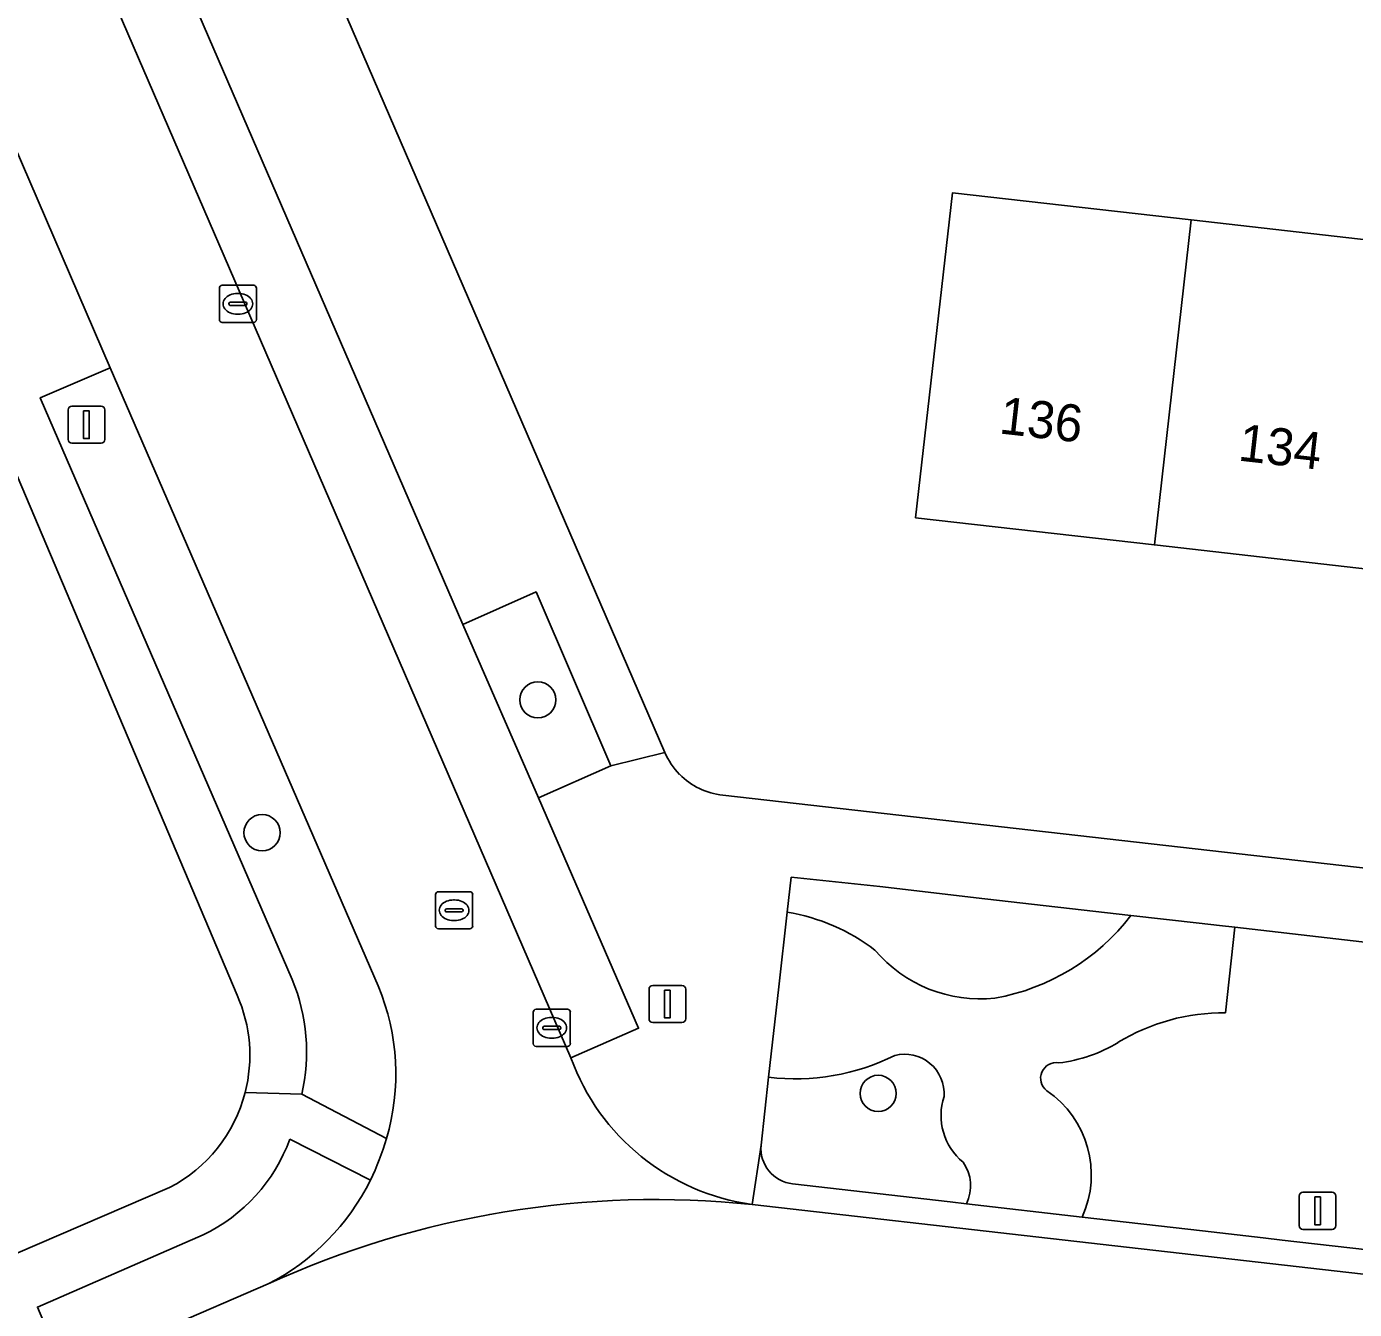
# Model space of a CAD drawing. Extents: x 162026 to 163502, y 387295 to 388169.
# Drawn here: x 162241.43 to 162277.28, y 387988.1 to 388022.74 of the extents above; entities that cross this region are included whole.
import ezdxf

# ---------------------------------------------------------------- set-up
doc = ezdxf.new("R2010")
doc.units = 0
for name, color, linetype in [('IMGEO_Boom', 7, 'Continuous'), ('IMGEO_Erf', 7, 'Continuous'), ('IMGEO_Groenvoorziening', 7, 'Continuous'), ('IMGEO_Kolk', 7, 'Continuous'), ('IMGEO_Lichtmast', 7, 'Continuous'), ('IMGEO_Pand', 7, 'Continuous'), ('IMGEO_Pand_nummerreeks', 7, 'Continuous'), ('IMGEO_Parkeervlak_open', 7, 'Continuous'), ('IMGEO_Rijbaan_lokaal_open', 7, 'Continuous'), ('IMGEO_Rioolput', 7, 'Continuous'), ('IMGEO_Voetpad_open', 7, 'Continuous')]:
    doc.layers.add(name, color=color, linetype=linetype)

msp = doc.modelspace()

# ---------------------------------------------------------------- linework, layer by layer
at = {"layer": 'IMGEO_Boom'}
for centre in [(162255.234, 388004.559), (162247.788, 388000.972), (162264.422, 387993.931)]:
    msp.add_circle(centre, 0.489, dxfattribs=at)
at = {"layer": 'IMGEO_Erf'}
for points in [[(162299.337, 388025.532), (162289.611, 388026.623), (162289.188, 388022.806), (162286.544, 388023.099), (162283.9, 388023.392), (162284.323, 388027.209), (162276.998, 388028.02), (162276.575, 388024.203), (162273.921, 388024.497), (162271.278, 388024.79), (162271.7, 388028.607), (162270.784, 388028.723), (162270.329, 388028.733), (162270.019, 388028.709), (162269.435, 388028.585), (162250.08, 388022.997), (162258.662, 388003.139)], [(162247.117, 387996.582), (162240.422, 388012.373)], [(162260.226, 388001.984), (162277.731, 388000), (162292.907, 387998.354), (162293.134, 387998.329)], [(162231.639, 387985.507), (162245.293, 387991.388)]]:
    msp.add_lwpolyline(points, dxfattribs=at)
msp.add_lwpolyline([(162279.335, 388016.79), (162279.673, 388019.771), (162286.03, 388019.05), (162292.043, 388018.368), (162291.704, 388015.385), (162292.241, 388015.324), (162291.244, 388006.545), (162284.696, 388007.289), (162278.339, 388008.01), (162271.878, 388008.744), (162265.433, 388009.476), (162266.429, 388018.255), (162272.875, 388017.523)], close=True, dxfattribs=at)
for centre, radius, start, end in [((162260.416, 388003.89), 1.908, 203.1954, 224.72), ((162260.432, 388003.898), 1.925, 224.5303, 263.8431), ((162243.429, 387994.956), 4.03, 345.5537, 23.7898), ((162243.434, 387994.96), 4.027, 297.4986, 345.4932)]:
    msp.add_arc(centre, radius, start, end, dxfattribs=at)
at = {"layer": 'IMGEO_Groenvoorziening'}
for points in [[(162243.691, 388013.525), (162241.8, 388012.719), (162248.605, 387997.004)], [(162250.922, 387996.833), (162243.691, 388013.525)], [(162271.244, 387998.739), (162267.305, 387999.189), (162264.468, 387999.514), (162262.073, 387999.77), (162261.967, 387998.826)], [(162261.967, 387998.826), (162261.74, 387996.813), (162261.465, 387994.365)], [(162274.047, 387998.418), (162273.64, 387998.465), (162273.085, 387998.528), (162271.244, 387998.739)], [(162273.802, 387996.107), (162274.047, 387998.418)], [(162284.991, 387997.166), (162282.29, 387997.475), (162281.785, 387997.533), (162279.507, 387997.794), (162274.047, 387998.418), (162273.802, 387996.107)], [(162269.927, 387990.591), (162273.177, 387990.217), (162274.818, 387990.029), (162275.326, 387989.971), (162280.015, 387989.433), (162283.986, 387988.977), (162284.111, 387988.963), (162284.576, 387993.299), (162284.991, 387997.166)], [(162261.465, 387994.365), (162261.259, 387992.534)], [(162248.859, 387993.907), (162251.148, 387992.708)], [(162250.717, 387991.588), (162248.537, 387992.693)], [(162262.113, 387991.488), (162266.366, 387991), (162266.807, 387990.949)], [(162266.807, 387990.949), (162269.927, 387990.591)], [(162246.195, 387990.109), (162241.722, 387988.158), (162242.466, 387986.409), (162247.956, 387988.784)]]:
    msp.add_lwpolyline(points, dxfattribs=at)
msp.add_lwpolyline([(162255.188, 388007.476), (162253.211, 388006.595), (162255.25, 388001.914), (162257.203, 388002.781)], close=True, dxfattribs=at)
for centre, radius, start, end in [((162261.086, 387993.546), 5.353, 52.6247, 80.5234), ((162261.086, 387993.546), 5.353, 52.6247, 80.5234), ((162266.56, 388002.302), 5.885, 279.9183, 322.7411), ((162266.56, 388002.302), 5.885, 279.9183, 322.7411), ((162267.173, 388000.201), 3.717, 220.2268, 276.1887), ((162267.173, 388000.201), 3.717, 220.2268, 276.1887), ((162243.849, 387995.055), 5.14, 347.0935, 22.2838), ((162245.219, 387994.452), 6.18, 343.6106, 22.6614), ((162273.756, 387990.603), 5.505, 89.5202, 121.2405), ((162273.756, 387990.603), 5.505, 89.5202, 121.2405), ((162268.883, 387998.552), 3.819, 276.236, 301.8945), ((162268.883, 387998.552), 3.819, 276.236, 301.8945), ((162262.177, 388000.359), 6.036, 263.228, 296.4979), ((162262.177, 388000.359), 6.036, 263.228, 296.4979), ((162265.133, 387993.92), 1.07, 356.1314, 104.2236), ((162265.133, 387993.92), 1.07, 356.1314, 104.2236), ((162269.229, 387994.339), 0.422, 80.6533, 232.729), ((162269.229, 387994.339), 0.422, 80.6533, 232.729), ((162267.759, 387993.335), 1.641, 161.7948, 230.4109), ((162267.759, 387993.335), 1.641, 161.7948, 230.4109), ((162267.428, 387991.732), 2.748, 335.464, 55.747), ((162267.428, 387991.732), 2.748, 335.464, 55.747), ((162244.203, 387994.267), 4.611, 295.5909, 340.0341), ((162262.224, 387992.45), 0.969, 175.0512, 263.4082), ((162265.824, 387991.432), 1.095, 333.8593, 35.7187), ((162265.824, 387991.432), 1.095, 333.8593, 35.7187), ((162245.037, 387994.419), 6.346, 297.3808, 333.5046)]:
    msp.add_arc(centre, radius, start, end, dxfattribs=at)
at = {"layer": 'IMGEO_Kolk'}
for p, q in [((162246.636, 388014.829), (162246.636, 388015.681)), ((162246.711, 388015.755), (162247.563, 388015.755)), ((162247.637, 388015.681), (162247.637, 388014.829)), ((162246.938, 388015.298), (162247.336, 388015.298)), ((162247.124, 388015.535), (162247.149, 388015.535)), ((162246.895, 388015.249), (162246.895, 388015.261)), ((162247.333, 388015.212), (162246.935, 388015.212)), ((162247.147, 388014.975), (162247.122, 388014.975)), ((162247.379, 388015.261), (162247.379, 388015.249)), ((162247.563, 388014.755), (162246.711, 388014.755)), ((162255.11, 387995.275), (162255.11, 387996.127)), ((162255.185, 387996.201), (162256.037, 387996.201)), ((162255.598, 387995.981), (162255.623, 387995.981)), ((162256.111, 387996.127), (162256.111, 387995.275)), ((162255.369, 387995.695), (162255.369, 387995.707)), ((162255.807, 387995.658), (162255.409, 387995.658)), ((162255.412, 387995.744), (162255.81, 387995.744)), ((162255.853, 387995.707), (162255.853, 387995.695)), ((162256.037, 387995.201), (162255.185, 387995.201)), ((162255.621, 387995.421), (162255.596, 387995.421))]:
    msp.add_line(p, q, dxfattribs=at)
for points in [[(162246.636, 388014.829), (162246.636, 388015.681)], [(162246.711, 388015.755), (162247.563, 388015.755)], [(162247.637, 388015.681), (162247.637, 388014.829)], [(162247.563, 388014.755), (162246.711, 388014.755)], [(162255.11, 387995.275), (162255.11, 387996.127)], [(162255.185, 387996.201), (162256.037, 387996.201)], [(162256.111, 387996.127), (162256.111, 387995.275)], [(162256.037, 387995.201), (162255.185, 387995.201)]]:
    msp.add_lwpolyline(points, dxfattribs=at)
for centre, radius, start, end in [((162246.713, 388015.679), 0.0765, 91.552, 178.448), ((162246.713, 388015.679), 0.0765, 91.552, 178.448), ((162247.561, 388015.679), 0.0765, 1.552, 88.448), ((162247.561, 388015.679), 0.0765, 1.552, 88.448), ((162246.935, 388015.258), 0.0403, 85.8775, 175.7526), ((162247.34, 388015.26), 0.0386, 1.7309, 96.639), ((162246.932, 388015.248), 0.0366, 178.938, 274.7102), ((162247.336, 388015.255), 0.043, 264.8664, 352.4533), ((162246.713, 388014.831), 0.0765, 181.552, 268.448), ((162246.713, 388014.831), 0.0765, 181.552, 268.448), ((162247.561, 388014.831), 0.0765, 271.552, 358.448), ((162247.561, 388014.831), 0.0765, 271.552, 358.448), ((162255.187, 387996.125), 0.0765, 91.552, 178.448), ((162255.187, 387996.125), 0.0765, 91.552, 178.448), ((162256.035, 387996.125), 0.0765, 1.552, 88.448), ((162256.035, 387996.125), 0.0765, 1.552, 88.448), ((162255.409, 387995.704), 0.0403, 85.8775, 175.7526), ((162255.406, 387995.694), 0.0366, 178.938, 274.7102), ((162255.81, 387995.701), 0.043, 264.8664, 352.4533), ((162255.814, 387995.706), 0.0386, 1.7309, 96.639), ((162255.187, 387995.277), 0.0765, 181.552, 268.448), ((162255.187, 387995.277), 0.0765, 181.552, 268.448), ((162256.035, 387995.277), 0.0765, 271.552, 358.448), ((162256.035, 387995.277), 0.0765, 271.552, 358.448)]:
    msp.add_arc(centre, radius, start, end, dxfattribs=at)
for centre, major_axis, ratio, start_param, end_param in [((162247.123, 388015.255), (-0.387, 0.002), 0.722429, 4.712389, 7.853982), ((162247.148, 388015.255), (-0.39, 0.002), 0.717154, 1.570796, 4.712389), ((162255.597, 387995.701), (-0.387, 0.002), 0.722429, 4.712389, 7.853982), ((162255.622, 387995.701), (-0.39, 0.002), 0.717154, 1.570796, 4.712389)]:
    msp.add_ellipse(centre, major_axis=major_axis, ratio=ratio, start_param=start_param, end_param=end_param, dxfattribs=at)
at = {"layer": 'IMGEO_Lichtmast'}
for p, q in [((162242.652, 388012.49), (162243.442, 388012.49)), ((162243.442, 388012.49), (162242.652, 388012.49)), ((162242.552, 388011.59), (162242.552, 388012.39)), ((162242.552, 388012.39), (162242.552, 388011.59)), ((162243.542, 388012.39), (162243.542, 388011.59)), ((162243.542, 388011.59), (162243.542, 388012.39)), ((162243.442, 388011.49), (162242.652, 388011.49)), ((162242.652, 388011.49), (162243.442, 388011.49)), ((162258.235, 387995.943), (162258.235, 387996.743)), ((162258.235, 387996.743), (162258.235, 387995.943)), ((162258.335, 387996.843), (162259.125, 387996.843)), ((162259.125, 387996.843), (162258.335, 387996.843)), ((162259.225, 387996.743), (162259.225, 387995.943)), ((162259.225, 387995.943), (162259.225, 387996.743)), ((162259.125, 387995.843), (162258.335, 387995.843)), ((162258.335, 387995.843), (162259.125, 387995.843)), ((162275.889, 387991.259), (162276.679, 387991.259)), ((162276.679, 387991.259), (162275.889, 387991.259)), ((162275.789, 387990.359), (162275.789, 387991.159)), ((162275.789, 387991.159), (162275.789, 387990.359)), ((162276.779, 387991.159), (162276.779, 387990.359)), ((162276.779, 387990.359), (162276.779, 387991.159)), ((162276.679, 387990.259), (162275.889, 387990.259)), ((162275.889, 387990.259), (162276.679, 387990.259))]:
    msp.add_line(p, q, dxfattribs=at)
for points in [[(162242.972, 388012.365), (162243.122, 388012.365), (162243.122, 388011.615), (162242.972, 388011.615), (162242.972, 388012.365)], [(162258.655, 387996.718), (162258.805, 387996.718), (162258.805, 387995.968), (162258.655, 387995.968), (162258.655, 387996.718)], [(162276.209, 387991.134), (162276.359, 387991.134), (162276.359, 387990.384), (162276.209, 387990.384), (162276.209, 387991.134)]]:
    msp.add_lwpolyline(points, dxfattribs=at)
for centre, start, end in [((162242.652, 388012.39), 90, 180), ((162242.652, 388012.39), 90, 180), ((162243.442, 388012.39), 0, 90), ((162243.442, 388012.39), 360, 90), ((162242.652, 388011.59), 180, 270), ((162242.652, 388011.59), 180, 270), ((162243.442, 388011.59), 270, 0), ((162243.442, 388011.59), 270, 0), ((162258.335, 387996.743), 90, 180), ((162258.335, 387996.743), 90, 180), ((162259.125, 387996.743), 0, 90), ((162259.125, 387996.743), 360, 90), ((162258.335, 387995.943), 180, 270), ((162258.335, 387995.943), 180, 270), ((162259.125, 387995.943), 270, 0), ((162259.125, 387995.943), 270, 0), ((162275.889, 387991.159), 90, 180), ((162275.889, 387991.159), 90, 180), ((162276.679, 387991.159), 0, 90), ((162276.679, 387991.159), 360, 90), ((162275.889, 387990.359), 180, 270), ((162275.889, 387990.359), 180, 270), ((162276.679, 387990.359), 270, 0), ((162276.679, 387990.359), 270, 0)]:
    msp.add_arc(centre, 0.1, start, end, dxfattribs=at)
at = {"layer": 'IMGEO_Pand'}
for points in [[(162272.875, 388017.523), (162266.429, 388018.255), (162265.433, 388009.476), (162271.878, 388008.744)], [(162279.335, 388016.79), (162272.875, 388017.523), (162271.878, 388008.744), (162278.339, 388008.01)]]:
    msp.add_lwpolyline(points, close=True, dxfattribs=at)
at = {"layer": 'IMGEO_Parkeervlak_open'}
msp.add_lwpolyline([(162233.87, 388051.368), (162229.312, 388061.864), (162227.416, 388066.277), (162222.488, 388077.667), (162220.499, 388082.24), (162219.67, 388084.193), (162217.803, 388083.405), (162232.4, 388049.731), (162233.78, 388046.56), (162247.319, 388015.274), (162256.129, 387994.89), (162257.953, 387995.69), (162255.25, 388001.914), (162253.211, 388006.595), (162245.674, 388024.015), (162243.789, 388028.432), (162235.771, 388046.953)], close=True, dxfattribs=at)
at = {"layer": 'IMGEO_Rijbaan_lokaal_open'}
for points in [[(162247.319, 388015.274), (162233.78, 388046.56), (162230.114, 388044.937), (162231.893, 388040.822), (162234.759, 388034.257), (162240.871, 388020.067), (162243.691, 388013.525), (162250.922, 387996.833)], [(162256.129, 387994.89), (162247.319, 388015.274)], [(162256.533, 387986.755), (162268.637, 387985.369), (162274.652, 387984.68), (162287.36, 387983.225), (162287.971, 387987.874), (162285.183, 387988.176), (162261.021, 387990.93)], [(162247.956, 387988.784), (162242.466, 387986.409), (162238.329, 387984.653), (162222.983, 387978.072), (162216.634, 387975.343), (162203.22, 387969.54)]]:
    msp.add_lwpolyline(points, dxfattribs=at)
for centre, radius, start, end in [((162245.219, 387994.452), 6.18, 343.6106, 22.6614), ((162261.856, 387996.963), 6.091, 199.9005, 262.1202), ((162243.864, 387994.868), 7.597, 334.4223, 343.4821), ((162245.037, 387994.419), 6.346, 297.3808, 333.5046), ((162258.425, 387965.894), 25.17, 84.0791, 114.5767), ((162258.425, 387965.894), 25.17, 84.0791, 114.5767)]:
    msp.add_arc(centre, radius, start, end, dxfattribs=at)
at = {"layer": 'IMGEO_Rioolput'}
for p, q in [((162252.473, 387998.45), (162252.473, 387999.302)), ((162252.548, 387999.376), (162253.4, 387999.376)), ((162252.961, 387999.156), (162252.986, 387999.156)), ((162253.474, 387999.302), (162253.474, 387998.45)), ((162252.732, 387998.87), (162252.732, 387998.882)), ((162253.17, 387998.833), (162252.772, 387998.833)), ((162252.775, 387998.919), (162253.173, 387998.919)), ((162253.216, 387998.882), (162253.216, 387998.87)), ((162252.984, 387998.596), (162252.959, 387998.596)), ((162253.4, 387998.376), (162252.548, 387998.376))]:
    msp.add_line(p, q, dxfattribs=at)
for points in [[(162252.473, 387998.45), (162252.473, 387999.302)], [(162252.548, 387999.376), (162253.4, 387999.376)], [(162253.474, 387999.302), (162253.474, 387998.45)], [(162253.4, 387998.376), (162252.548, 387998.376)]]:
    msp.add_lwpolyline(points, dxfattribs=at)
for centre, radius, start, end in [((162252.55, 387999.3), 0.0765, 91.552, 178.448), ((162252.55, 387999.3), 0.0765, 91.552, 178.448), ((162253.398, 387999.3), 0.0765, 1.552, 88.448), ((162253.398, 387999.3), 0.0765, 1.552, 88.448), ((162252.772, 387998.879), 0.0403, 85.8775, 175.7526), ((162252.769, 387998.869), 0.0366, 178.938, 274.7102), ((162253.173, 387998.876), 0.043, 264.8664, 352.4533), ((162253.177, 387998.881), 0.0386, 1.7309, 96.639), ((162252.55, 387998.452), 0.0765, 181.552, 268.448), ((162252.55, 387998.452), 0.0765, 181.552, 268.448), ((162253.398, 387998.452), 0.0765, 271.552, 358.448), ((162253.398, 387998.452), 0.0765, 271.552, 358.448)]:
    msp.add_arc(centre, radius, start, end, dxfattribs=at)
for centre, major_axis, ratio, start_param, end_param in [((162252.96, 387998.876), (-0.387, 0.002), 0.722429, 4.712389, 7.853982), ((162252.985, 387998.876), (-0.39, 0.002), 0.717154, 1.570796, 4.712389)]:
    msp.add_ellipse(centre, major_axis=major_axis, ratio=ratio, start_param=start_param, end_param=end_param, dxfattribs=at)
at = {"layer": 'IMGEO_Voetpad_open'}
for points in [[(162207.72, 388088.631), (162207.867, 388087.996), (162208.124, 388087.243), (162208.345, 388086.704), (162208.535, 388086.273), (162211.796, 388078.889), (162213.178, 388075.685), (162215.914, 388069.339), (162217.745, 388065.052), (162220.184, 388059.405), (162220.404, 388058.948), (162240.422, 388012.373), (162247.117, 387996.582)], [(162248.605, 387997.004), (162241.8, 388012.719), (162243.691, 388013.525), (162240.871, 388020.067), (162238.987, 388019.237), (162232.785, 388033.424)], [(162245.674, 388024.015), (162253.211, 388006.595), (162255.188, 388007.476), (162257.203, 388002.781), (162258.662, 388003.139), (162250.08, 388022.997)], [(162258.662, 388003.139), (162257.203, 388002.781), (162255.25, 388001.914), (162257.953, 387995.69), (162256.129, 387994.89)], [(162277.731, 388000), (162260.226, 388001.984)], [(162261.021, 387990.93), (162261.259, 387992.534), (162261.465, 387994.365), (162261.74, 387996.813), (162261.967, 387998.826), (162262.073, 387999.77), (162264.468, 387999.514), (162267.305, 387999.189), (162271.244, 387998.739), (162273.085, 387998.528), (162273.64, 387998.465), (162274.047, 387998.418), (162279.507, 387997.794), (162281.785, 387997.533), (162282.29, 387997.475), (162284.991, 387997.166), (162294.329, 387996.098)], [(162247.332, 387993.951), (162248.859, 387993.907)], [(162251.148, 387992.708), (162248.859, 387993.907), (162247.332, 387993.951)], [(162248.537, 387992.693), (162250.717, 387991.588)], [(162261.259, 387992.534), (162261.021, 387990.93), (162285.183, 387988.176), (162287.971, 387987.874), (162288.149, 387987.855), (162294.103, 387987.216), (162294.16, 387987.809), (162284.478, 387988.92), (162284.111, 387988.963), (162283.986, 387988.977), (162280.015, 387989.433), (162275.326, 387989.971)], [(162245.293, 387991.388), (162231.639, 387985.507), (162227.318, 387983.646), (162221.922, 387981.322), (162220.083, 387980.53), (162219.814, 387980.414), (162217.334, 387979.346), (162216.865, 387979.144), (162215.755, 387978.666), (162214.34, 387978.057), (162212.118, 387977.1), (162209.156, 387975.824), (162201.794, 387972.653)], [(162275.326, 387989.971), (162274.818, 387990.029), (162273.177, 387990.217), (162269.927, 387990.591), (162266.807, 387990.949), (162266.366, 387991), (162262.113, 387991.488)], [(162237.562, 387986.4), (162238.329, 387984.653), (162242.466, 387986.409), (162241.722, 387988.158), (162246.195, 387990.109)]]:
    msp.add_lwpolyline(points, dxfattribs=at)
for centre, radius, start, end in [((162260.416, 388003.89), 1.908, 203.1954, 224.72), ((162260.432, 388003.898), 1.925, 224.5303, 263.8431), ((162243.849, 387995.055), 5.14, 347.0935, 22.2838), ((162243.429, 387994.956), 4.03, 345.5537, 23.7898), ((162261.856, 387996.963), 6.091, 199.9005, 262.1202), ((162243.434, 387994.96), 4.027, 297.4986, 345.4932), ((162244.203, 387994.267), 4.611, 295.5909, 340.0341), ((162243.864, 387994.868), 7.597, 334.4223, 343.4821), ((162262.224, 387992.45), 0.969, 175.0512, 263.4082)]:
    msp.add_arc(centre, radius, start, end, dxfattribs=at)

# ---------------------------------------------------------------- texts
at = {"layer": 'IMGEO_Pand_nummerreeks'}
for s, p in [('136', (162267.665, 388011.758)), ('134', (162274.117, 388011.025))]:
    msp.add_text(s, height=1, rotation=353.5215, dxfattribs=at).set_placement(p)

doc.saveas('drawing.dxf')
